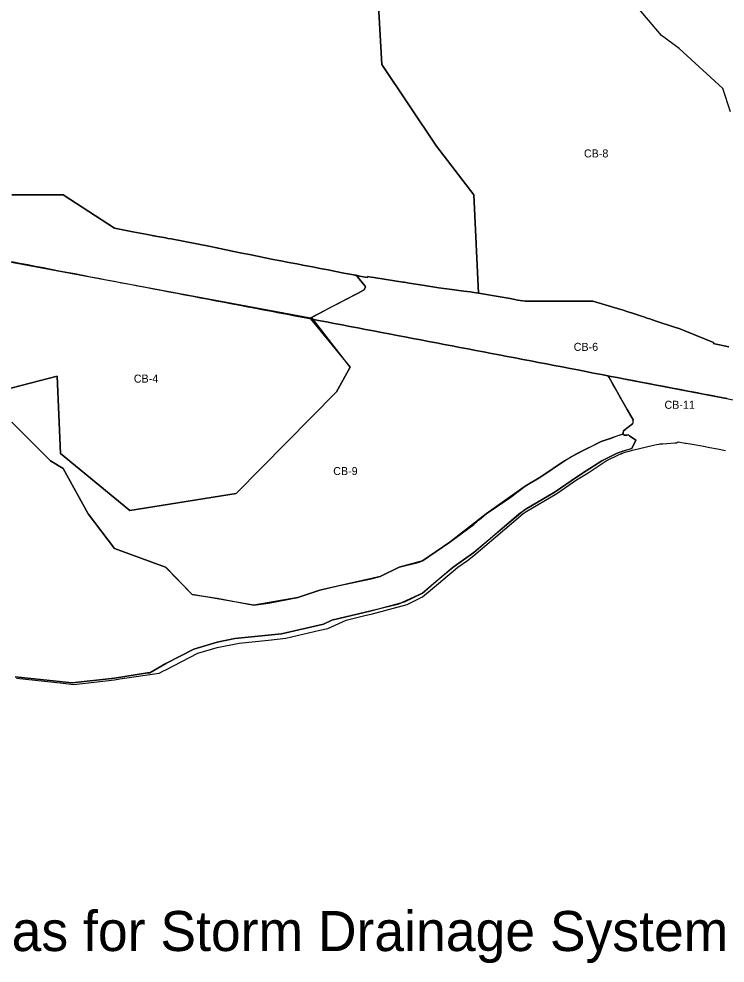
# Model space of a CAD drawing. Extents: x 2451 to 3960, y 2751 to 3762.
# Drawn here: x 2980 to 3422, y 2751 to 3341 of the extents above; entities that cross this region are included whole.
import ezdxf

# ---------------------------------------------------------------- set-up
doc = ezdxf.new("R2010")
doc.units = 0
doc.layers.add('SURVEY - DRAINAGE - Area Shapes', color=7, linetype='Continuous')
doc.layers.add('SURVEY - DRAINAGE - Area Shapes Text', color=7, linetype='Continuous')

msp = doc.modelspace()

# ---------------------------------------------------------------- linework, layer by layer
at = {"layer": 'SURVEY - DRAINAGE - Area Shapes'}
for p, q in [((3191.93, 3179.59), (3191.26, 3180.37)), ((3364, 3088.62), (3364, 3088.63)), ((3359.45, 3080.97), (3359.15, 3081)), ((3359.71, 3080.94), (3359.45, 3080.97)), ((3360.01, 3080.93), (3359.71, 3080.94)), ((3360.27, 3080.96), (3360.01, 3080.93)), ((3361.04, 3081.13), (3360.27, 3080.96))]:
    msp.add_line(p, q, dxfattribs=at)
for points in [[(3424.85, 3282.93), (3420.16, 3297.38), (3392.77, 3322.42), (3381.74, 3330.56), (3360.69, 3355.49), (3331.96, 3360.29), (3327.79, 3363.75), (3296.54, 3380.84), (3256.72, 3404.95), (3209.15, 3420.97), (3200.31, 3430.12), (3207.11, 3312.52), (3241.27, 3261.49), (3264.46, 3231), (3267.42, 3169.7)], [(3264.46, 3231), (3241.27, 3261.49), (3207.11, 3312.52), (3200.31, 3430.12)], [(3191.26, 3180.37), (3190.89, 3180.81), (3188.19, 3181.32), (3183.28, 3182.26), (3178.37, 3183.2), (3173.46, 3184.14), (3168.55, 3185.08), (3163.64, 3186.02), (3158.73, 3186.96), (3153.82, 3187.9), (3148.91, 3188.84), (3144, 3189.78), (3139.08, 3190.72), (3134.17, 3191.66), (3134.16, 3191.79), (3129.28, 3192.71), (3124.39, 3193.72), (3119.49, 3194.73), (3114.59, 3195.74), (3109.69, 3196.75), (3104.8, 3197.77), (3104.61, 3197.81), (3104.08, 3197.92), (3103.95, 3197.94), (3099.89, 3198.73), (3075.36, 3203.54), (3073.38, 3203.9), (3072, 3204.15), (3065.52, 3205.32), (3064.9, 3205.43), (3064.58, 3205.49), (3060.6, 3206.21), (3051.51, 3207.95), (3039.92, 3210.17), (3007.85, 3231), (2975.77, 3231)], [(2975.77, 3231), (3007.85, 3231), (3039.92, 3210.17), (3051.51, 3207.95), (3060.6, 3206.21), (3064.58, 3205.49), (3064.9, 3205.43), (3065.52, 3205.32), (3072, 3204.15), (3073.38, 3203.9), (3075.36, 3203.54), (3099.89, 3198.73), (3103.95, 3197.94), (3104.08, 3197.92), (3104.61, 3197.81), (3104.8, 3197.77), (3109.69, 3196.75), (3114.59, 3195.74), (3119.49, 3194.73), (3124.39, 3193.72), (3129.28, 3192.71), (3134.16, 3191.79), (3134.17, 3191.66), (3139.08, 3190.72), (3144, 3189.78), (3148.91, 3188.84), (3153.82, 3187.9), (3158.73, 3186.96)], [(3197.98, 3179.45), (3198.13, 3180.06), (3200.31, 3179.72), (3202.07, 3179.44), (3220.15, 3176.57), (3220.96, 3176.44), (3224.14, 3175.94), (3232.38, 3174.63), (3242.6, 3173.01), (3245.76, 3172.65), (3247.58, 3172.44), (3258.32, 3170.98), (3262.47, 3170.41), (3264.46, 3170.13), (3267.42, 3169.7), (3264.46, 3231)], [(2975.92, 3189.36), (2980.83, 3188.42), (2985.74, 3187.48), (2990.65, 3186.54), (2995.56, 3185.6), (3000.48, 3184.66), (3005.39, 3183.72), (3010.3, 3182.78), (3015.21, 3181.85), (3020.12, 3180.9), (3025.03, 3179.96), (3029.94, 3179.03), (3034.85, 3178.09), (3039.76, 3177.15), (3044.67, 3176.21), (3049.58, 3175.27), (3054.5, 3174.33), (3059.41, 3173.39), (3064.32, 3172.45), (3069.23, 3171.51), (3074.14, 3170.57), (3079.05, 3169.63), (3083.96, 3168.69)], [(3158.73, 3186.96), (3163.64, 3186.02), (3168.55, 3185.08), (3173.46, 3184.14), (3178.37, 3183.2), (3183.28, 3182.26), (3188.19, 3181.32), (3193.1, 3180.38), (3197.98, 3179.45), (3197.98, 3179.45)], [(3423.92, 3136.21), (3414.13, 3138.29), (3414.14, 3138.42), (3414.14, 3138.45), (3414.15, 3138.55), (3414.15, 3138.59), (3414.16, 3138.69), (3414.16, 3138.72), (3414.16, 3138.72), (3414.16, 3138.74), (3414.16, 3138.74), (3414.16, 3138.75), (3414.17, 3138.78), (3396.31, 3146.16), (3394.28, 3147), (3392.77, 3147.51), (3390.4, 3148.32), (3377.82, 3152.45), (3374.39, 3153.59), (3372.63, 3154.16), (3371.23, 3154.62), (3369.95, 3155.04), (3365.55, 3156.5), (3364.79, 3156.75), (3363, 3157.34), (3360.69, 3158.1), (3358.4, 3158.86), (3357.45, 3159.17), (3356.31, 3159.54), (3338.83, 3164.62), (3328.62, 3164.62), (3296.54, 3164.62), (3292.05, 3165.38), (3287.12, 3166.25), (3282.2, 3167.12), (3277.27, 3167.98), (3272.35, 3168.84), (3267.42, 3169.7), (3264.46, 3170.13), (3262.47, 3170.41), (3258.32, 3170.98), (3247.58, 3172.44), (3245.76, 3172.65), (3242.6, 3173.01), (3232.38, 3174.63), (3224.14, 3175.94), (3220.96, 3176.44), (3220.15, 3176.57), (3202.07, 3179.44), (3200.31, 3179.72), (3198.13, 3180.06), (3197.98, 3179.45), (3197.98, 3179.45), (3193.1, 3180.38), (3190.89, 3180.81), (3196.64, 3174.11), (3196.84, 3173.56), (3195.88, 3171.71), (3192.18, 3169.76), (3190.95, 3169.12), (3161.74, 3153.81), (3162.54, 3153.65), (3167.45, 3152.71), (3172.36, 3151.77), (3177.27, 3150.83), (3182.18, 3149.89), (3187.09, 3148.95), (3192, 3148.01), (3196.91, 3147.07), (3201.82, 3146.13), (3206.73, 3145.19), (3211.64, 3144.25), (3216.55, 3143.31), (3221.47, 3142.37), (3226.38, 3141.43), (3231.29, 3140.49), (3236.2, 3139.56), (3241.11, 3138.62), (3246.02, 3137.68), (3250.93, 3136.74), (3255.84, 3135.8), (3260.75, 3134.86), (3265.66, 3133.92), (3270.57, 3132.98), (3275.49, 3132.04), (3280.4, 3131.1), (3285.31, 3130.16), (3290.22, 3129.22), (3295.13, 3128.28), (3300.04, 3127.34), (3304.95, 3126.4), (3309.86, 3125.46), (3314.77, 3124.52), (3319.68, 3123.58), (3324.59, 3122.64), (3329.51, 3121.7), (3334.42, 3120.76), (3339.33, 3119.82), (3344.24, 3118.88), (3349.15, 3117.94), (3354.06, 3117), (3358.97, 3116.06)], [(3196.84, 3173.56), (3196.84, 3173.56), (3196.84, 3173.57), (3196.64, 3174.11), (3192.77, 3178.62), (3192.38, 3179.07), (3191.93, 3179.59)], [(3192.18, 3169.76), (3195.88, 3171.71), (3195.99, 3171.92), (3196.84, 3173.56)], [(3083.96, 3168.69), (3088.87, 3167.75), (3093.78, 3166.81), (3098.69, 3165.87), (3103.6, 3164.93), (3108.52, 3163.99), (3113.43, 3163.05), (3118.34, 3162.11), (3123.25, 3161.17), (3128.16, 3160.23), (3133.07, 3159.29), (3137.98, 3158.35), (3142.89, 3157.41), (3147.8, 3156.47), (3152.71, 3155.53), (3161.74, 3153.81), (3161.74, 3153.81), (3162.43, 3154.17)], [(3179.43, 3163.08), (3179.63, 3163.19), (3183.68, 3165.31), (3185.29, 3166.15), (3188.5, 3167.84), (3190.95, 3169.12), (3192.18, 3169.76)], [(3267.42, 3169.7), (3272.35, 3168.84), (3277.27, 3167.98), (3282.2, 3167.12), (3287.12, 3166.25), (3292.05, 3165.38), (3296.54, 3164.62), (3328.62, 3164.62), (3338.83, 3164.62), (3356.31, 3159.54), (3357.45, 3159.17), (3358.4, 3158.86), (3360.69, 3158.1), (3363, 3157.34), (3364.79, 3156.75), (3365.55, 3156.5), (3369.95, 3155.04), (3371.23, 3154.62), (3372.63, 3154.16), (3374.39, 3153.59), (3377.82, 3152.45), (3390.4, 3148.32), (3392.77, 3147.51), (3394.28, 3147), (3396.31, 3146.16), (3414.17, 3138.78), (3414.16, 3138.75), (3414.16, 3138.74), (3414.16, 3138.74), (3414.16, 3138.72), (3414.16, 3138.72), (3414.16, 3138.69), (3414.15, 3138.59), (3414.15, 3138.55), (3414.14, 3138.45), (3414.14, 3138.42), (3414.13, 3138.29), (3423.92, 3136.21)], [(3162.43, 3154.17), (3162.66, 3154.29), (3163.11, 3154.53), (3168.32, 3157.25), (3170.93, 3158.62), (3173.97, 3160.22), (3175.18, 3160.85), (3178.81, 3162.76), (3179.43, 3163.08)], [(3351.32, 3112.86), (3348.97, 3116.99), (3348.34, 3118.1), (3344.24, 3118.88), (3339.33, 3119.82), (3334.42, 3120.76), (3329.51, 3121.7), (3324.59, 3122.64), (3319.68, 3123.58), (3314.77, 3124.52), (3309.86, 3125.46), (3304.95, 3126.4), (3300.04, 3127.34), (3295.13, 3128.28), (3290.22, 3129.22), (3285.31, 3130.16), (3280.4, 3131.1), (3275.49, 3132.04), (3270.57, 3132.98), (3265.66, 3133.92), (3260.75, 3134.86), (3255.84, 3135.8), (3250.93, 3136.74), (3246.02, 3137.68), (3241.11, 3138.62), (3236.2, 3139.56), (3231.29, 3140.49), (3226.38, 3141.43), (3221.47, 3142.37), (3216.55, 3143.31), (3211.64, 3144.25), (3206.73, 3145.19), (3201.82, 3146.13), (3196.91, 3147.07), (3192, 3148.01), (3187.09, 3148.95), (3182.18, 3149.89), (3177.27, 3150.83), (3172.36, 3151.77), (3167.45, 3152.71), (3162.54, 3153.65), (3187.16, 3123.41), (3178.69, 3108.14), (3116.05, 3044.49), (3049.56, 3033.88), (3006.19, 3069.56), (3004.26, 3117.78), (2970.53, 3109.1)], [(3422.81, 3103.84), (3417.9, 3104.78), (3412.99, 3105.72), (3408.08, 3106.66), (3403.17, 3107.6), (3398.26, 3108.54), (3393.35, 3109.48), (3388.44, 3110.42), (3383.53, 3111.36), (3378.61, 3112.3), (3373.7, 3113.24), (3368.79, 3114.18), (3363.88, 3115.12), (3358.97, 3116.06), (3354.06, 3117), (3349.15, 3117.94), (3348.34, 3118.1), (3348.97, 3116.99), (3357, 3102.9), (3360.4, 3096.94), (3363.98, 3090.67), (3363.71, 3088.17), (3358.9, 3084.33), (3358.06, 3083.66), (3357.59, 3081.62), (3358.72, 3081.06), (3360.01, 3080.93), (3361.04, 3081.13), (3361.8, 3080.61), (3365.73, 3077.97), (3363.15, 3072.74), (3354.06, 3069.85), (3344.39, 3065.06), (3334.75, 3058.72), (3328.62, 3054.88), (3315.25, 3045.7), (3296.54, 3034.64), (3264.46, 3007.85), (3251.53, 2998.69), (3232.38, 2982.45), (3216.97, 2975.35), (3175.84, 2965.5), (3170.56, 2963.09), (3144.35, 2957.02), (3115.24, 2953.95), (3104.08, 2951.71), (3089.53, 2947.36), (3072, 2938.36), (3061.99, 2932.57), (3060.67, 2932.55), (3039.92, 2929.21), (3013.64, 2926.32), (2977.86, 2930.15)], [(3358.97, 3116.06), (3457.19, 3097.27), (3462.1, 3096.33), (3467.01, 3095.39), (3471.92, 3094.45), (3475.92, 3093.68), (3477.04, 3094.57), (3480.71, 3097.51)], [(3357, 3102.9), (3356.59, 3103.62), (3356.16, 3104.38), (3352.78, 3110.31), (3351.32, 3112.86)], [(3364, 3088.63), (3364, 3088.66), (3363.99, 3089.11), (3363.98, 3090.67), (3360.4, 3096.94), (3357, 3102.9)], [(2975.77, 3089.06), (3000.01, 3065.06), (3007.85, 3060.28), (3023.58, 3031.88)], [(3359.15, 3081), (3358.72, 3081.06), (3358.1, 3081.42), (3357.59, 3081.62), (3344.08, 3077.05), (3326.5, 3068.17), (3321.04, 3065.06), (3306.31, 3054.95), (3296.54, 3049.17), (3272.14, 3031.88), (3249.45, 3014.22), (3232.38, 3002.48), (3217.93, 2998.69), (3205.98, 2992.82), (3168.23, 2984.18), (3154.62, 2979.58), (3127.07, 2974.9), (3088.61, 2981.5), (3071.77, 2998.69), (3039.92, 3010.21), (3023.58, 3031.88), (3007.85, 3060.28), (3000.01, 3065.06), (2975.77, 3089.06)], [(3357.48, 3081.59), (3357.59, 3081.62), (3358.03, 3083.55), (3358.04, 3083.59), (3358.06, 3083.66), (3358.9, 3084.33), (3359.08, 3084.48), (3361.15, 3086.13)], [(3361.15, 3086.13), (3363.71, 3088.17), (3363.71, 3088.18), (3363.86, 3088.41), (3364, 3088.62)], [(2977.86, 2930.15), (3007.85, 2926.96), (3013.64, 2926.32), (3039.92, 2929.21), (3039.92, 2929.21), (3060.67, 2932.55), (3061.99, 2932.57), (3072, 2938.36), (3089.53, 2947.36), (3104.08, 2951.71), (3115.24, 2953.95), (3144.35, 2957.02), (3170.56, 2963.09), (3175.84, 2965.5), (3200.31, 2971.34), (3221.28, 2976.99), (3232.38, 2982.45), (3241.01, 2989.76), (3251.53, 2998.69), (3264.46, 3007.85), (3292.64, 3031.88), (3296.54, 3034.64), (3315.25, 3045.7), (3328.62, 3054.88), (3334.75, 3058.72), (3344.39, 3065.06), (3354.06, 3069.85), (3356.37, 3070.64), (3357.83, 3071.14), (3361.49, 3072.33), (3363.15, 3072.74), (3363.15, 3072.74), (3365.73, 3077.97), (3361.8, 3080.61), (3361.04, 3081.13)], [(3023.58, 3031.88), (3039.92, 3010.21), (3071.77, 2998.69), (3072, 2998.53), (3088.61, 2981.5), (3104.08, 2979.31), (3127.07, 2974.9), (3136.15, 2976.21), (3154.62, 2979.58), (3168.23, 2984.18), (3179.56, 2986.96), (3200.31, 2991.29), (3205.98, 2992.82), (3217.93, 2998.69), (3229.63, 3001.53), (3232.38, 3002.48), (3249.45, 3014.22), (3264.46, 3025.33), (3267.94, 3028.28), (3272.14, 3031.88), (3286.95, 3041.8), (3296.54, 3049.17), (3306.31, 3054.95), (3321.04, 3065.06), (3325.54, 3067.61), (3325.81, 3067.76), (3325.94, 3067.83), (3326.12, 3067.94), (3326.5, 3068.17), (3326.99, 3068.45), (3327.06, 3068.49), (3327.61, 3068.81), (3328.44, 3069.3), (3328.62, 3069.39), (3329.59, 3069.89), (3344.08, 3077.05), (3346.58, 3077.91), (3347.85, 3078.35), (3349.85, 3079.03), (3353.52, 3080.29), (3357.48, 3081.59)], [(2978.78, 2929.2), (3007.85, 2926.11), (3014.56, 2925.36), (3039.92, 2928.15), (3043.33, 2928.79), (3067.83, 2932.31), (3070.59, 2933.77), (3072, 2934.55), (3091.99, 2944.82), (3104.08, 2948.44), (3117.9, 2951.2), (3136.15, 2953.1), (3146.99, 2954.29), (3168.23, 2959.27), (3173.26, 2960.3), (3184.69, 2965.5), (3197.31, 2968.61), (3200.31, 2969.23), (3222.9, 2975.31), (3232.38, 2979.97), (3242.33, 2988.4), (3254.45, 2998.69), (3260.46, 3002.83), (3264.46, 3005.78), (3278.32, 3017.53), (3295.07, 3031.88), (3295.96, 3032.47), (3296.54, 3032.92), (3316.31, 3044.61), (3328.62, 3053.06), (3335.84, 3057.58), (3347.21, 3065.06), (3355.21, 3069.02), (3356.03, 3069.3), (3356.45, 3069.45), (3357.11, 3069.67), (3358.33, 3070.09), (3359.63, 3070.52), (3360.69, 3070.86), (3361.35, 3071.08), (3361.52, 3071.12), (3363.59, 3071.63), (3376.65, 3074.68), (3378.58, 3075.13), (3380.23, 3075.45), (3380.98, 3075.6), (3382.49, 3075.69), (3389.99, 3076.18), (3391.28, 3076.26), (3391.31, 3076.29), (3391.41, 3076.38), (3391.44, 3076.4), (3391.44, 3076.4), (3391.44, 3076.4), (3391.53, 3076.44), (3391.69, 3076.6), (3391.91, 3076.6), (3392.18, 3076.76), (3396.48, 3075.96), (3397.13, 3076.03), (3402.07, 3075.23), (3406.98, 3074.29), (3411.89, 3073.35), (3416.8, 3072.41), (3421.71, 3071.48)]]:
    msp.add_lwpolyline(points, dxfattribs=at)
msp.add_lwpolyline([(2939.7, 3163.1), (2970.53, 3109.1), (3004.26, 3117.78), (3006.19, 3069.56), (3049.56, 3033.88), (3116.05, 3044.49), (3178.69, 3108.14), (3187.16, 3123.41), (3163.77, 3153.84), (2917.21, 3199.58), (2941.21, 3171.81), (2941.55, 3169.36), (2941.04, 3168.82), (2933.29, 3164.94)], close=True, dxfattribs=at)

# ---------------------------------------------------------------- texts
at = {"layer": 'SURVEY - DRAINAGE - Area Shapes Text'}
for s, height, p in [('CB-8', 5, (3333.3, 3254.42)), ('CB-6', 5, (3326.91, 3133.66)), ('CB-4', 5, (3052.07, 3113.83)), ('CB-11', 5, (3383.63, 3097.48)), ('CB-9', 5, (3176.65, 3056.11)), ('Drainage Areas for Storm Drainage System', 25, (2778.76, 2758.91))]:
    msp.add_text(s, height=height, dxfattribs=at).set_placement(p)

doc.saveas('drawing.dxf')
